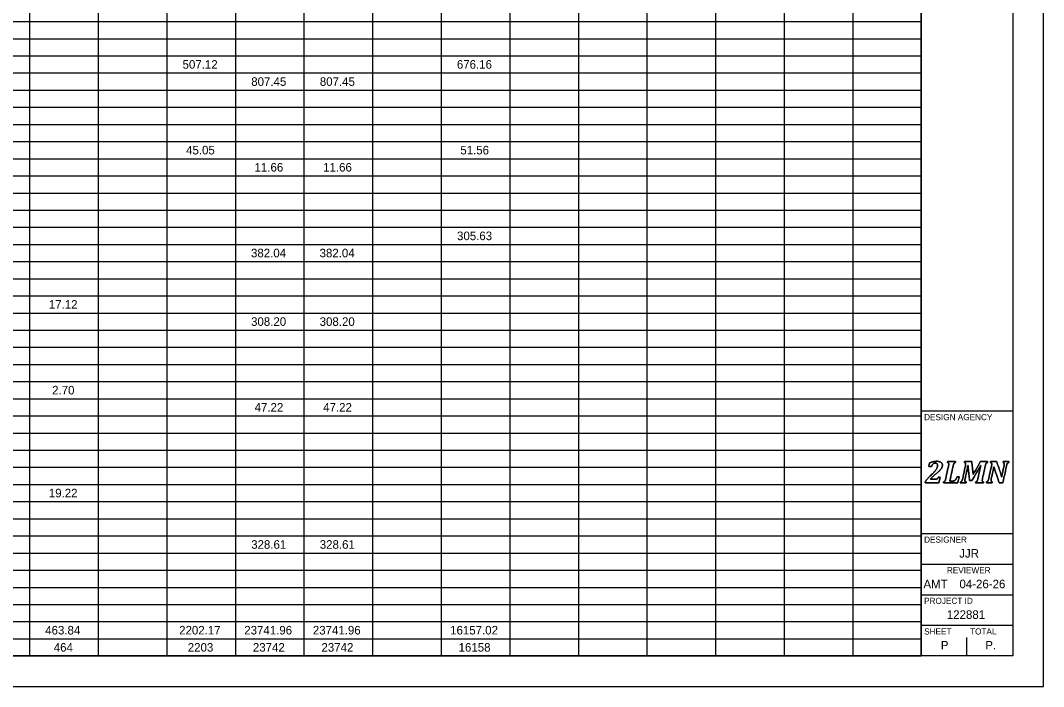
# Model space of a CAD drawing. Extents: x 0 to 34, y 0 to 22.
# Drawn here: x 17.29 to 34, y 0 to 10.88 of the extents above; entities that cross this region are included whole.
import ezdxf

# ---------------------------------------------------------------- set-up
doc = ezdxf.new("R2010")
doc.units = 0
for name, color, linetype in [('SH_Border', 7, 'Continuous'), ('SH_Cut_Line', 7, 'Continuous'), ('SH_Data', 7, 'Continuous'), ('SH_Text', 7, 'Continuous')]:
    doc.layers.add(name, color=color, linetype=linetype)

msp = doc.modelspace()

# ---------------------------------------------------------------- linework, layer by layer
at = {"layer": 'SH_Border'}
for p, q in [((32, 0.5), (32, 21.5)), ((32, 4.5), (33.5, 4.5)), ((32, 2.5), (33.5, 2.5)), ((32, 2), (33.5, 2)), ((32, 1.5), (33.5, 1.5)), ((32, 1), (33.5, 1))]:
    msp.add_line(p, q, dxfattribs=at)
msp.add_lwpolyline([(1.5, 21.5), (33.5, 21.5), (33.5, 0.5), (1.5, 0.5)], close=True, dxfattribs=at)
at = {"layer": 'SH_Cut_Line'}
msp.add_lwpolyline([(0, 0), (34, 0), (34, 22), (0, 22)], close=True, dxfattribs=at)
at = {"layer": 'SH_Data'}
for p, q in [((32.75, 3.5), (32.75, 3.5)), ((32.375, 0.675), (32.375, 0.675)), ((32.75, 0.5), (32.75, 0.8))]:
    msp.add_line(p, q, dxfattribs=at)
for points in [[(32.237, 3.388), (32.246, 3.388), (32.253, 3.389), (32.258, 3.39), (32.263, 3.392), (32.267, 3.394), (32.27, 3.397), (32.273, 3.401), (32.277, 3.408), (32.281, 3.417), (32.281, 3.417), (32.312, 3.417), (32.312, 3.417), (32.312, 3.417), (32.29, 3.326), (32.29, 3.326), (32.29, 3.326), (32.066, 3.326), (32.066, 3.326), (32.066, 3.326), (32.069, 3.343), (32.069, 3.343), (32.078, 3.358), (32.091, 3.375), (32.106, 3.394), (32.122, 3.412), (32.144, 3.435), (32.172, 3.462), (32.197, 3.486), (32.217, 3.506), (32.23, 3.521), (32.243, 3.537), (32.253, 3.551), (32.259, 3.566), (32.266, 3.58), (32.269, 3.595), (32.269, 3.61), (32.269, 3.622), (32.266, 3.632), (32.26, 3.64), (32.253, 3.647), (32.245, 3.65), (32.234, 3.65), (32.22, 3.65), (32.208, 3.646), (32.198, 3.636), (32.188, 3.627), (32.18, 3.613), (32.172, 3.593), (32.172, 3.593), (32.126, 3.593), (32.126, 3.593), (32.126, 3.593), (32.14, 3.654), (32.14, 3.654), (32.166, 3.663), (32.188, 3.669), (32.205, 3.673), (32.223, 3.676), (32.24, 3.678), (32.258, 3.678), (32.278, 3.678), (32.295, 3.675), (32.309, 3.669), (32.322, 3.664), (32.332, 3.656), (32.339, 3.646), (32.345, 3.637), (32.348, 3.626), (32.348, 3.613), (32.348, 3.602), (32.346, 3.591), (32.342, 3.581), (32.339, 3.571), (32.333, 3.56), (32.324, 3.549), (32.315, 3.539), (32.304, 3.526), (32.289, 3.513), (32.275, 3.499), (32.254, 3.482), (32.228, 3.46), (32.216, 3.45), (32.202, 3.438), (32.188, 3.425), (32.174, 3.412), (32.162, 3.4), (32.154, 3.391), (32.154, 3.391), (32.153, 3.388), (32.153, 3.388), (32.153, 3.388), (32.237, 3.388), (32.237, 3.388)], [(32.237, 3.388), (32.237, 3.388), (32.153, 3.388), (32.153, 3.388), (32.153, 3.388), (32.154, 3.391), (32.154, 3.391), (32.162, 3.4), (32.174, 3.412), (32.188, 3.425), (32.202, 3.438), (32.216, 3.45), (32.228, 3.46), (32.254, 3.482), (32.275, 3.499), (32.289, 3.513), (32.304, 3.526), (32.315, 3.539), (32.324, 3.549), (32.333, 3.56), (32.339, 3.571), (32.342, 3.581), (32.346, 3.591), (32.348, 3.602), (32.348, 3.613), (32.348, 3.626), (32.345, 3.637), (32.339, 3.646), (32.332, 3.656), (32.322, 3.664), (32.309, 3.669), (32.295, 3.675), (32.278, 3.678), (32.258, 3.678), (32.24, 3.678), (32.223, 3.676), (32.205, 3.673), (32.188, 3.669), (32.166, 3.663), (32.14, 3.654), (32.14, 3.654), (32.126, 3.593), (32.126, 3.593), (32.126, 3.593), (32.172, 3.593), (32.172, 3.593), (32.18, 3.613), (32.188, 3.627), (32.198, 3.636), (32.208, 3.646), (32.22, 3.65), (32.234, 3.65), (32.245, 3.65), (32.253, 3.647), (32.26, 3.64), (32.266, 3.632), (32.269, 3.622), (32.269, 3.61), (32.269, 3.595), (32.266, 3.58), (32.259, 3.566), (32.253, 3.551), (32.243, 3.537), (32.23, 3.521), (32.217, 3.506), (32.197, 3.486), (32.172, 3.462), (32.144, 3.435), (32.122, 3.412), (32.106, 3.394), (32.091, 3.375), (32.078, 3.358), (32.069, 3.343), (32.069, 3.343), (32.066, 3.326), (32.066, 3.326), (32.066, 3.326), (32.29, 3.326), (32.29, 3.326), (32.29, 3.326), (32.312, 3.417), (32.312, 3.417), (32.312, 3.417), (32.281, 3.417), (32.281, 3.417), (32.277, 3.408), (32.273, 3.401), (32.27, 3.397), (32.267, 3.394), (32.263, 3.392), (32.258, 3.39), (32.253, 3.389), (32.246, 3.388), (32.237, 3.388)], [(32.518, 3.356), (32.527, 3.356), (32.533, 3.357), (32.538, 3.358), (32.542, 3.36), (32.546, 3.362), (32.55, 3.365), (32.554, 3.368), (32.558, 3.372), (32.562, 3.377), (32.567, 3.382), (32.571, 3.388), (32.576, 3.397), (32.58, 3.405), (32.585, 3.415), (32.589, 3.427), (32.589, 3.427), (32.624, 3.427), (32.624, 3.427), (32.624, 3.427), (32.598, 3.326), (32.598, 3.326), (32.598, 3.326), (32.365, 3.326), (32.365, 3.326), (32.365, 3.326), (32.369, 3.343), (32.369, 3.343), (32.376, 3.345), (32.381, 3.348), (32.385, 3.351), (32.389, 3.355), (32.392, 3.36), (32.395, 3.366), (32.398, 3.373), (32.4, 3.382), (32.403, 3.395), (32.403, 3.395), (32.449, 3.605), (32.449, 3.605), (32.452, 3.615), (32.453, 3.625), (32.453, 3.635), (32.453, 3.642), (32.451, 3.647), (32.448, 3.651), (32.444, 3.654), (32.439, 3.656), (32.432, 3.657), (32.432, 3.657), (32.435, 3.674), (32.435, 3.674), (32.435, 3.674), (32.563, 3.674), (32.563, 3.674), (32.563, 3.674), (32.559, 3.657), (32.559, 3.657), (32.552, 3.655), (32.547, 3.652), (32.543, 3.649), (32.539, 3.645), (32.536, 3.64), (32.533, 3.634), (32.531, 3.627), (32.528, 3.618), (32.525, 3.605), (32.525, 3.605), (32.47, 3.356), (32.47, 3.356), (32.47, 3.356), (32.518, 3.356), (32.518, 3.356)], [(32.518, 3.356), (32.518, 3.356), (32.47, 3.356), (32.47, 3.356), (32.47, 3.356), (32.525, 3.605), (32.525, 3.605), (32.528, 3.618), (32.531, 3.627), (32.533, 3.634), (32.536, 3.64), (32.539, 3.645), (32.543, 3.649), (32.547, 3.652), (32.552, 3.655), (32.559, 3.657), (32.559, 3.657), (32.563, 3.674), (32.563, 3.674), (32.563, 3.674), (32.435, 3.674), (32.435, 3.674), (32.435, 3.674), (32.432, 3.657), (32.432, 3.657), (32.439, 3.656), (32.444, 3.654), (32.448, 3.651), (32.451, 3.647), (32.453, 3.642), (32.453, 3.635), (32.453, 3.625), (32.452, 3.615), (32.449, 3.605), (32.449, 3.605), (32.403, 3.395), (32.403, 3.395), (32.4, 3.382), (32.398, 3.373), (32.395, 3.366), (32.392, 3.36), (32.389, 3.355), (32.385, 3.351), (32.381, 3.348), (32.376, 3.345), (32.369, 3.343), (32.369, 3.343), (32.365, 3.326), (32.365, 3.326), (32.365, 3.326), (32.598, 3.326), (32.598, 3.326), (32.598, 3.326), (32.624, 3.427), (32.624, 3.427), (32.624, 3.427), (32.589, 3.427), (32.589, 3.427), (32.585, 3.415), (32.58, 3.405), (32.576, 3.397), (32.571, 3.388), (32.567, 3.382), (32.562, 3.377), (32.558, 3.372), (32.554, 3.368), (32.55, 3.365), (32.546, 3.362), (32.542, 3.36), (32.538, 3.358), (32.533, 3.357), (32.527, 3.356), (32.518, 3.356)], [(32.829, 3.674), (32.829, 3.674), (32.849, 3.461), (32.849, 3.461), (32.849, 3.461), (32.969, 3.674), (32.969, 3.674), (32.969, 3.674), (33.087, 3.674), (33.087, 3.674), (33.087, 3.674), (33.084, 3.657), (33.084, 3.657), (33.077, 3.655), (33.071, 3.652), (33.067, 3.649), (33.064, 3.645), (33.06, 3.64), (33.058, 3.634), (33.055, 3.627), (33.052, 3.618), (33.05, 3.605), (33.05, 3.605), (33.003, 3.395), (33.003, 3.395), (33.002, 3.39), (33.002, 3.387), (33.001, 3.384), (33.001, 3.382), (33.001, 3.379), (33, 3.376), (33, 3.373), (33, 3.369), (33, 3.365), (33, 3.358), (33.002, 3.353), (33.005, 3.349), (33.008, 3.346), (33.014, 3.344), (33.021, 3.343), (33.021, 3.343), (33.018, 3.326), (33.018, 3.326), (33.018, 3.326), (32.89, 3.326), (32.89, 3.326), (32.89, 3.326), (32.893, 3.343), (32.893, 3.343), (32.9, 3.345), (32.906, 3.348), (32.91, 3.351), (32.914, 3.355), (32.917, 3.36), (32.919, 3.366), (32.922, 3.373), (32.925, 3.382), (32.928, 3.395), (32.928, 3.395), (32.951, 3.502), (32.951, 3.502), (32.954, 3.513), (32.957, 3.529), (32.962, 3.548), (32.967, 3.568), (32.972, 3.588), (32.978, 3.609), (32.978, 3.609), (32.973, 3.609), (32.973, 3.609), (32.965, 3.594), (32.957, 3.579), (32.948, 3.563), (32.948, 3.563), (32.833, 3.364), (32.833, 3.364), (32.833, 3.364), (32.792, 3.364), (32.792, 3.364), (32.792, 3.364), (32.775, 3.518), (32.775, 3.518), (32.773, 3.537), (32.772, 3.554), (32.77, 3.569), (32.769, 3.583), (32.768, 3.597), (32.768, 3.611), (32.768, 3.611), (32.764, 3.611), (32.764, 3.611), (32.761, 3.596), (32.758, 3.578), (32.755, 3.558), (32.751, 3.538), (32.747, 3.521), (32.744, 3.507), (32.744, 3.507), (32.72, 3.395), (32.72, 3.395), (32.719, 3.39), (32.718, 3.387), (32.718, 3.384), (32.717, 3.382), (32.717, 3.379), (32.717, 3.376), (32.717, 3.373), (32.716, 3.369), (32.716, 3.365), (32.716, 3.358), (32.718, 3.353), (32.721, 3.349), (32.725, 3.346), (32.73, 3.344), (32.738, 3.343), (32.738, 3.343), (32.734, 3.326), (32.734, 3.326), (32.734, 3.326), (32.641, 3.326), (32.641, 3.326), (32.641, 3.326), (32.644, 3.343), (32.644, 3.343), (32.651, 3.345), (32.657, 3.348), (32.661, 3.351), (32.665, 3.355), (32.668, 3.36), (32.67, 3.366), (32.673, 3.373), (32.676, 3.382), (32.679, 3.395), (32.679, 3.395), (32.725, 3.605), (32.725, 3.605), (32.727, 3.615), (32.728, 3.625), (32.728, 3.635), (32.728, 3.642), (32.727, 3.647), (32.723, 3.651), (32.72, 3.654), (32.715, 3.656), (32.707, 3.657), (32.707, 3.657), (32.711, 3.674), (32.711, 3.674), (32.711, 3.674), (32.829, 3.674), (32.829, 3.674)], [(32.829, 3.674), (32.829, 3.674), (32.711, 3.674), (32.711, 3.674), (32.711, 3.674), (32.707, 3.657), (32.707, 3.657), (32.715, 3.656), (32.72, 3.654), (32.723, 3.651), (32.727, 3.647), (32.728, 3.642), (32.728, 3.635), (32.728, 3.625), (32.727, 3.615), (32.725, 3.605), (32.725, 3.605), (32.679, 3.395), (32.679, 3.395), (32.676, 3.382), (32.673, 3.373), (32.67, 3.366), (32.668, 3.36), (32.665, 3.355), (32.661, 3.351), (32.657, 3.348), (32.651, 3.345), (32.644, 3.343), (32.644, 3.343), (32.641, 3.326), (32.641, 3.326), (32.641, 3.326), (32.734, 3.326), (32.734, 3.326), (32.734, 3.326), (32.738, 3.343), (32.738, 3.343), (32.73, 3.344), (32.725, 3.346), (32.721, 3.349), (32.718, 3.353), (32.716, 3.358), (32.716, 3.365), (32.716, 3.369), (32.717, 3.373), (32.717, 3.376), (32.717, 3.379), (32.717, 3.382), (32.718, 3.384), (32.718, 3.387), (32.719, 3.39), (32.72, 3.395), (32.72, 3.395), (32.744, 3.507), (32.744, 3.507), (32.747, 3.521), (32.751, 3.538), (32.755, 3.558), (32.758, 3.578), (32.761, 3.596), (32.764, 3.611), (32.764, 3.611), (32.768, 3.611), (32.768, 3.611), (32.768, 3.597), (32.769, 3.583), (32.77, 3.569), (32.772, 3.554), (32.773, 3.537), (32.775, 3.518), (32.775, 3.518), (32.792, 3.364), (32.792, 3.364), (32.792, 3.364), (32.833, 3.364), (32.833, 3.364), (32.833, 3.364), (32.948, 3.563), (32.948, 3.563), (32.957, 3.579), (32.965, 3.594), (32.973, 3.609), (32.973, 3.609), (32.978, 3.609), (32.978, 3.609), (32.972, 3.588), (32.967, 3.568), (32.962, 3.548), (32.957, 3.529), (32.954, 3.513), (32.951, 3.502), (32.951, 3.502), (32.928, 3.395), (32.928, 3.395), (32.925, 3.382), (32.922, 3.373), (32.919, 3.366), (32.917, 3.36), (32.914, 3.355), (32.91, 3.351), (32.906, 3.348), (32.9, 3.345), (32.893, 3.343), (32.893, 3.343), (32.89, 3.326), (32.89, 3.326), (32.89, 3.326), (33.018, 3.326), (33.018, 3.326), (33.018, 3.326), (33.021, 3.343), (33.021, 3.343), (33.014, 3.344), (33.008, 3.346), (33.005, 3.349), (33.002, 3.353), (33, 3.358), (33, 3.365), (33, 3.369), (33, 3.373), (33, 3.376), (33.001, 3.379), (33.001, 3.382), (33.001, 3.384), (33.002, 3.387), (33.002, 3.39), (33.003, 3.395), (33.003, 3.395), (33.05, 3.605), (33.05, 3.605), (33.052, 3.618), (33.055, 3.627), (33.058, 3.634), (33.06, 3.64), (33.064, 3.645), (33.067, 3.649), (33.071, 3.652), (33.077, 3.655), (33.084, 3.657), (33.084, 3.657), (33.087, 3.674), (33.087, 3.674), (33.087, 3.674), (32.969, 3.674), (32.969, 3.674), (32.969, 3.674), (32.849, 3.461), (32.849, 3.461), (32.849, 3.461), (32.829, 3.674), (32.829, 3.674)], [(33.137, 3.674), (33.137, 3.674), (33.234, 3.674), (33.234, 3.674), (33.234, 3.674), (33.283, 3.53), (33.283, 3.53), (33.296, 3.49), (33.307, 3.456), (33.315, 3.426), (33.315, 3.426), (33.318, 3.426), (33.318, 3.426), (33.323, 3.455), (33.329, 3.488), (33.337, 3.523), (33.337, 3.523), (33.355, 3.605), (33.355, 3.605), (33.357, 3.615), (33.358, 3.625), (33.358, 3.635), (33.358, 3.642), (33.357, 3.647), (33.353, 3.651), (33.35, 3.654), (33.345, 3.656), (33.337, 3.657), (33.337, 3.657), (33.341, 3.674), (33.341, 3.674), (33.341, 3.674), (33.434, 3.674), (33.434, 3.674), (33.434, 3.674), (33.431, 3.657), (33.431, 3.657), (33.424, 3.655), (33.418, 3.652), (33.414, 3.649), (33.41, 3.645), (33.407, 3.64), (33.405, 3.634), (33.402, 3.627), (33.399, 3.618), (33.396, 3.605), (33.396, 3.605), (33.335, 3.326), (33.335, 3.326), (33.335, 3.326), (33.277, 3.326), (33.277, 3.326), (33.277, 3.326), (33.216, 3.504), (33.216, 3.504), (33.211, 3.518), (33.207, 3.531), (33.204, 3.543), (33.2, 3.556), (33.195, 3.571), (33.19, 3.59), (33.19, 3.59), (33.186, 3.59), (33.186, 3.59), (33.185, 3.579), (33.182, 3.563), (33.179, 3.543), (33.175, 3.523), (33.17, 3.501), (33.165, 3.478), (33.165, 3.478), (33.147, 3.395), (33.147, 3.395), (33.146, 3.39), (33.145, 3.387), (33.145, 3.384), (33.144, 3.382), (33.144, 3.379), (33.144, 3.376), (33.143, 3.373), (33.143, 3.369), (33.143, 3.365), (33.143, 3.358), (33.145, 3.353), (33.148, 3.349), (33.152, 3.346), (33.157, 3.344), (33.164, 3.343), (33.164, 3.343), (33.161, 3.326), (33.161, 3.326), (33.161, 3.326), (33.067, 3.326), (33.067, 3.326), (33.067, 3.326), (33.071, 3.343), (33.071, 3.343), (33.078, 3.345), (33.083, 3.348), (33.087, 3.351), (33.091, 3.355), (33.094, 3.36), (33.097, 3.366), (33.1, 3.373), (33.102, 3.382), (33.105, 3.395), (33.105, 3.395), (33.151, 3.605), (33.151, 3.605), (33.154, 3.615), (33.155, 3.625), (33.155, 3.635), (33.155, 3.642), (33.153, 3.647), (33.15, 3.651), (33.146, 3.654), (33.141, 3.656), (33.134, 3.657), (33.134, 3.657), (33.137, 3.674), (33.137, 3.674)], [(33.137, 3.674), (33.137, 3.674), (33.134, 3.657), (33.134, 3.657), (33.141, 3.656), (33.146, 3.654), (33.15, 3.651), (33.153, 3.647), (33.155, 3.642), (33.155, 3.635), (33.155, 3.625), (33.154, 3.615), (33.151, 3.605), (33.151, 3.605), (33.105, 3.395), (33.105, 3.395), (33.102, 3.382), (33.1, 3.373), (33.097, 3.366), (33.094, 3.36), (33.091, 3.355), (33.087, 3.351), (33.083, 3.348), (33.078, 3.345), (33.071, 3.343), (33.071, 3.343), (33.067, 3.326), (33.067, 3.326), (33.067, 3.326), (33.161, 3.326), (33.161, 3.326), (33.161, 3.326), (33.164, 3.343), (33.164, 3.343), (33.157, 3.344), (33.152, 3.346), (33.148, 3.349), (33.145, 3.353), (33.143, 3.358), (33.143, 3.365), (33.143, 3.369), (33.143, 3.373), (33.144, 3.376), (33.144, 3.379), (33.144, 3.382), (33.145, 3.384), (33.145, 3.387), (33.146, 3.39), (33.147, 3.395), (33.147, 3.395), (33.165, 3.478), (33.165, 3.478), (33.17, 3.501), (33.175, 3.523), (33.179, 3.543), (33.182, 3.563), (33.185, 3.579), (33.186, 3.59), (33.186, 3.59), (33.19, 3.59), (33.19, 3.59), (33.195, 3.571), (33.2, 3.556), (33.204, 3.543), (33.207, 3.531), (33.211, 3.518), (33.216, 3.504), (33.216, 3.504), (33.277, 3.326), (33.277, 3.326), (33.277, 3.326), (33.335, 3.326), (33.335, 3.326), (33.335, 3.326), (33.396, 3.605), (33.396, 3.605), (33.399, 3.618), (33.402, 3.627), (33.405, 3.634), (33.407, 3.64), (33.41, 3.645), (33.414, 3.649), (33.418, 3.652), (33.424, 3.655), (33.431, 3.657), (33.431, 3.657), (33.434, 3.674), (33.434, 3.674), (33.434, 3.674), (33.341, 3.674), (33.341, 3.674), (33.341, 3.674), (33.337, 3.657), (33.337, 3.657), (33.345, 3.656), (33.35, 3.654), (33.353, 3.651), (33.357, 3.647), (33.358, 3.642), (33.358, 3.635), (33.358, 3.625), (33.357, 3.615), (33.355, 3.605), (33.355, 3.605), (33.337, 3.523), (33.337, 3.523), (33.329, 3.488), (33.323, 3.455), (33.318, 3.426), (33.318, 3.426), (33.315, 3.426), (33.315, 3.426), (33.307, 3.456), (33.296, 3.49), (33.283, 3.53), (33.283, 3.53), (33.234, 3.674), (33.234, 3.674), (33.234, 3.674), (33.137, 3.674), (33.137, 3.674)]]:
    msp.add_open_spline(points, degree=3, dxfattribs=at)
at = {"layer": 'SH_Text'}
for p, q in [((17.444, 21.5), (17.444, 0.5)), ((18.564, 21.5), (18.564, 0.5)), ((19.684, 21.5), (19.684, 0.5)), ((20.804, 21.5), (20.804, 0.5)), ((21.924, 21.5), (21.924, 0.5)), ((23.044, 21.5), (23.044, 0.5)), ((24.164, 21.5), (24.164, 0.5)), ((25.284, 21.5), (25.284, 0.5)), ((26.404, 21.5), (26.404, 0.5)), ((27.524, 21.5), (27.524, 0.5)), ((28.644, 21.5), (28.644, 0.5)), ((29.764, 21.5), (29.764, 0.5)), ((30.884, 21.5), (30.884, 0.5)), ((32.004, 21.5), (32.004, 0.5)), ((1.5, 10.86), (32.004, 10.86)), ((1.5, 10.58), (32.004, 10.58)), ((1.5, 10.3), (32.004, 10.3)), ((1.5, 10.02), (32.004, 10.02)), ((1.5, 9.74), (32.004, 9.74)), ((1.5, 9.46), (32.004, 9.46)), ((1.5, 9.18), (32.004, 9.18)), ((1.5, 8.9), (32.004, 8.9)), ((1.5, 8.62), (32.004, 8.62)), ((1.5, 8.34), (32.004, 8.34)), ((1.5, 8.06), (32.004, 8.06)), ((1.5, 7.78), (32.004, 7.78)), ((1.5, 7.5), (32.004, 7.5)), ((1.5, 7.22), (32.004, 7.22)), ((1.5, 6.94), (32.004, 6.94)), ((1.5, 6.66), (32.004, 6.66)), ((1.5, 6.38), (32.004, 6.38)), ((1.5, 6.1), (32.004, 6.1)), ((1.5, 5.82), (32.004, 5.82)), ((1.5, 5.54), (32.004, 5.54)), ((1.5, 5.26), (32.004, 5.26)), ((1.5, 4.98), (32.004, 4.98)), ((1.5, 4.7), (32.004, 4.7)), ((1.5, 4.42), (32.004, 4.42)), ((1.5, 4.14), (32.004, 4.14)), ((1.5, 3.86), (32.004, 3.86)), ((1.5, 3.58), (32.004, 3.58)), ((1.5, 3.3), (32.004, 3.3)), ((1.5, 3.02), (32.004, 3.02)), ((1.5, 2.74), (32.004, 2.74)), ((1.5, 2.46), (32.004, 2.46)), ((1.5, 2.18), (32.004, 2.18)), ((1.5, 1.9), (32.004, 1.9)), ((1.5, 1.62), (32.004, 1.62)), ((1.5, 1.34), (32.004, 1.34)), ((1.5, 1.06), (32.004, 1.06)), ((1.5, 0.78), (32.004, 0.78)), ((1.5, 0.5), (32.004, 0.5))]:
    msp.add_line(p, q, dxfattribs=at)

# ---------------------------------------------------------------- texts
at = {"layer": 'SH_Data'}
for s, height, p in [('DESIGN AGENCY', 0.1, (32.05, 4.35)), ('DESIGNER', 0.1, (32.05, 2.35)), ('JJR', 0.14, (32.624, 2.105)), ('REVIEWER', 0.1, (32.422, 1.85)), ('AMT', 0.14, (32.039, 1.605)), ('04-26-26', 0.14, (32.627, 1.605)), ('PROJECT ID', 0.1, (32.05, 1.35)), ('122881', 0.14, (32.421, 1.105)), ('SHEET', 0.1, (32.05, 0.85)), ('TOTAL', 0.1, (32.8, 0.85)), ('P', 0.14, (32.323, 0.605)), ('P.', 0.14, (33.048, 0.605))]:
    msp.add_text(s, height=height, dxfattribs=at).set_placement(p)
at = {"layer": 'SH_Text'}
for s, p in [('507.12', (19.942, 10.09)), ('676.16', (24.421, 10.09)), ('807.45', (21.063, 9.81)), ('807.45', (22.183, 9.81)), ('45.05', (19.999, 8.69)), ('51.56', (24.477, 8.69)), ('11.66', (21.117, 8.41)), ('11.66', (22.237, 8.41)), ('305.63', (24.423, 7.29)), ('382.04', (21.059, 7.01)), ('382.04', (22.179, 7.01)), ('17.12', (17.758, 6.17)), ('308.20', (21.06, 5.89)), ('308.20', (22.18, 5.89)), ('2.70', (17.812, 4.77)), ('47.22', (21.118, 4.49)), ('47.22', (22.238, 4.49)), ('19.22', (17.758, 3.09)), ('328.61', (21.062, 2.25)), ('328.61', (22.182, 2.25)), ('463.84', (17.699, 0.85)), ('2202.17', (19.886, 0.85)), ('23741.96', (20.949, 0.85)), ('23741.96', (22.069, 0.85)), ('16157.02', (24.311, 0.85)), ('464', (17.839, 0.57)), ('2203', (20.027, 0.57)), ('23742', (21.09, 0.57)), ('23742', (22.21, 0.57)), ('16158', (24.449, 0.57))]:
    msp.add_text(s, height=0.14, dxfattribs=at).set_placement(p)

doc.saveas('drawing.dxf')
